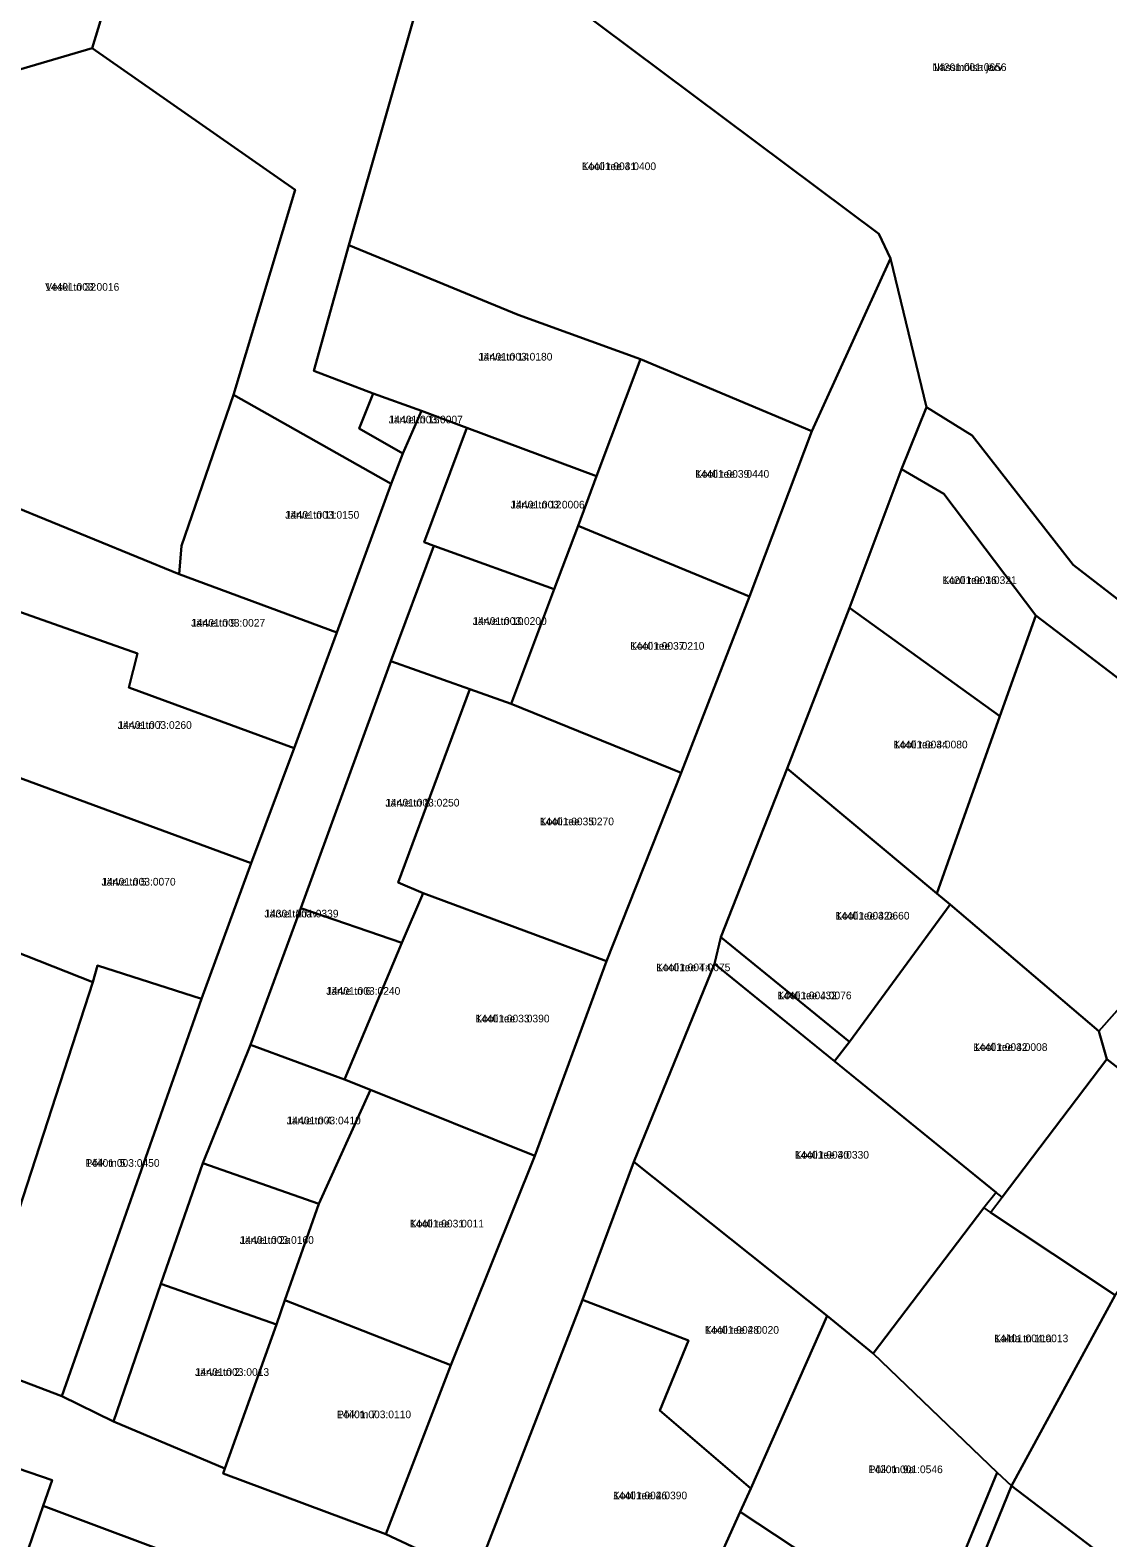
# Model space of a CAD drawing. Extents: x 640657 to 665127, y 6395726 to 6426831.
# Drawn here: x 650279.6 to 650490.5, y 6413110.9 to 6413405.9 of the extents above; entities that cross this region are included whole.
import ezdxf

# ---------------------------------------------------------------- set-up
doc = ezdxf.new("R2010")
doc.units = 0
for name, color, linetype in [('L_AADRESS', 7, 'Continuous'), ('PIIR', 7, 'Continuous'), ('TUNNUS', 7, 'Continuous')]:
    doc.layers.add(name, color=color, linetype=linetype)

msp = doc.modelspace()

# ---------------------------------------------------------------- linework, layer by layer
at = {"layer": 'PIIR'}
for points in [[(650239.68, 6413404.78), (650244.56, 6413436.52), (650296.67, 6413418.63), (650296.18, 6413417.03), (650291.72, 6413402.41), (650264, 6413394.25)], [(650296.18, 6413417.03), (650296.67, 6413418.63), (650313.26, 6413413.09), (650314.56, 6413413.9), (650316.99, 6413418.33), (650322.37, 6413433.84), (650323.18, 6413436.15), (650356.48, 6413416.32), (650356.93, 6413416.12), (650356.55, 6413414.99), (650341.99, 6413363.9), (650335.11, 6413339.3), (650346.72, 6413334.86), (650344.01, 6413327.96), (650352.56, 6413323.12), (650350.25, 6413317.19), (650319.38, 6413334.61), (650331.44, 6413374.73), (650291.72, 6413402.41)], [(650360.75, 6413429.64), (650445.67, 6413366.08), (650447.93, 6413361.29), (650432.57, 6413327.48), (650399.04, 6413341.57), (650375.12, 6413350.22), (650341.99, 6413363.9), (650356.55, 6413414.99), (650356.93, 6413416.12), (650357.5, 6413418.15)], [(650233.69, 6413371.67), (650239.68, 6413404.78), (650264, 6413394.25), (650291.72, 6413402.41), (650331.44, 6413374.73), (650319.38, 6413334.61), (650309.21, 6413305.01), (650308.77, 6413299.47), (650275.63, 6413313.03), (650260.72, 6413318.69), (650268.61, 6413358.41)], [(650390.43, 6413318.67), (650365.08, 6413328.14), (650356.21, 6413331.45), (650346.72, 6413334.86), (650335.11, 6413339.3), (650341.99, 6413363.9), (650375.12, 6413350.22), (650399.04, 6413341.57)], [(650447.93, 6413361.29), (650455.02, 6413332.18), (650450.1, 6413320), (650439.93, 6413292.9), (650427.74, 6413261.46), (650414.73, 6413228.41), (650413.5, 6413223.21), (650397.75, 6413184.5), (650387.68, 6413157.44), (650366.72, 6413103.36), (650349.21, 6413111.57), (650361.94, 6413144.67), (650378.35, 6413185.62), (650392.37, 6413223.71), (650406.97, 6413260.61), (650420.35, 6413295.13), (650432.57, 6413327.48)], [(650386.81, 6413308.95), (650390.43, 6413318.67), (650399.04, 6413341.57), (650432.57, 6413327.48), (650420.35, 6413295.13)], [(650319.38, 6413334.61), (650350.25, 6413317.19), (650339.6, 6413288.05), (650308.77, 6413299.47), (650309.21, 6413305.01)], [(650346.72, 6413334.86), (650356.21, 6413331.45), (650352.56, 6413323.12), (650344.01, 6413327.96)], [(650285.83, 6413138.63), (650313.15, 6413216.39), (650322.87, 6413242.9), (650331.25, 6413265.4), (650339.6, 6413288.05), (650350.25, 6413317.19), (650352.56, 6413323.12), (650356.21, 6413331.45), (650365.08, 6413328.14), (650356.68, 6413305.73), (650358.63, 6413305.03), (650350.16, 6413282.44), (650332.61, 6413234.09), (650322.72, 6413207.38), (650313.43, 6413184.18), (650305.16, 6413160.6), (650295.94, 6413133.65)], [(650450.1, 6413320), (650455.02, 6413332.18), (650463.94, 6413326.65), (650483.68, 6413301.28), (650535.03, 6413261.62), (650540.6, 6413257.3), (650543.8, 6413253.6), (650544.9, 6413251), (650553, 6413220.2), (650554.4, 6413215.1), (650558.34, 6413205.48), (650608.99, 6413156.91), (650603.97, 6413150.57), (650575.14, 6413177.06), (650575.61, 6413177.72), (650551.59, 6413195.75), (650543.11, 6413210.13), (650533.28, 6413247.75), (650511.53, 6413264.56), (650476.36, 6413291.39), (650458.4, 6413315.2)], [(650365.08, 6413328.14), (650390.43, 6413318.67), (650386.81, 6413308.95), (650382.17, 6413296.53), (650358.63, 6413305.03), (650356.68, 6413305.73)], [(650439.93, 6413292.9), (650450.1, 6413320), (650458.4, 6413315.2), (650476.36, 6413291.39), (650469.35, 6413271.66)], [(650339.6, 6413288.05), (650331.25, 6413265.4), (650298.94, 6413277.33), (650300.6, 6413283.97), (650267.91, 6413295.52), (650275.63, 6413313.03), (650308.77, 6413299.47)], [(650382.17, 6413296.53), (650386.81, 6413308.95), (650420.35, 6413295.13), (650406.97, 6413260.61), (650373.72, 6413274.09)], [(650350.16, 6413282.44), (650358.63, 6413305.03), (650382.17, 6413296.53), (650373.72, 6413274.09), (650365.62, 6413276.96)], [(650258.45, 6413274.81), (650267.91, 6413295.52), (650300.6, 6413283.97), (650298.94, 6413277.33), (650331.25, 6413265.4), (650322.87, 6413242.9), (650274.55, 6413260.7), (650277.16, 6413267.38)], [(650427.72, 6413261.48), (650439.93, 6413292.9), (650469.35, 6413271.66), (650463.49, 6413255.18), (650457.03, 6413237.01)], [(650511.53, 6413264.56), (650533.28, 6413247.75), (650522.77, 6413224.71), (650512.65, 6413202.51), (650494.29, 6413216.4), (650488.73, 6413210.04), (650459.61, 6413234.81), (650457.03, 6413237.01), (650463.49, 6413255.18), (650469.35, 6413271.66), (650476.36, 6413291.39)], [(650350.16, 6413282.44), (650365.62, 6413276.96), (650351.62, 6413239.13), (650356.48, 6413237.06), (650352.35, 6413227.35), (650332.61, 6413234.09)], [(650351.62, 6413239.13), (650365.62, 6413276.96), (650373.72, 6413274.09), (650406.97, 6413260.61), (650392.37, 6413223.71), (650356.48, 6413237.06)], [(650274.55, 6413260.7), (650322.87, 6413242.9), (650313.15, 6413216.39), (650292.79, 6413222.9), (650291.87, 6413219.64), (650262.95, 6413231.06)], [(650414.73, 6413228.41), (650427.74, 6413261.46), (650457.03, 6413237.01), (650459.61, 6413234.81), (650439.91, 6413207.97)], [(650246.99, 6413237.1), (650262.95, 6413231.06), (650291.87, 6413219.64), (650267.73, 6413145.46), (650223.38, 6413163.59)], [(650356.48, 6413237.06), (650392.37, 6413223.71), (650378.35, 6413185.62), (650346.19, 6413198.53), (650341.11, 6413200.59), (650352.35, 6413227.35)], [(650332.61, 6413234.09), (650352.35, 6413227.35), (650341.11, 6413200.59), (650322.72, 6413207.38)], [(650459.61, 6413234.81), (650488.73, 6413210.04), (650490.25, 6413204.53), (650469.82, 6413177.56), (650468.63, 6413178.49), (650436.96, 6413204.17), (650439.91, 6413207.97)], [(650414.73, 6413228.41), (650439.91, 6413207.97), (650436.96, 6413204.17), (650413.5, 6413223.21)], [(650291.87, 6413219.64), (650292.79, 6413222.9), (650313.15, 6413216.39), (650285.83, 6413138.63), (650267.73, 6413145.46)], [(650413.5, 6413223.21), (650468.63, 6413178.49), (650466.21, 6413175.44), (650444.55, 6413146.98), (650435.58, 6413154.3), (650397.75, 6413184.5)], [(650488.73, 6413210.04), (650494.29, 6413216.4), (650512.65, 6413202.51), (650530.63, 6413188.72), (650543.11, 6413210.13), (650551.59, 6413195.75), (650539.77, 6413179.73), (650533.54, 6413170.85), (650528.7, 6413174.65), (650513.56, 6413186.52), (650490.25, 6413204.53)], [(650322.72, 6413207.38), (650341.11, 6413200.59), (650346.19, 6413198.53), (650336.08, 6413176.24), (650313.43, 6413184.18)], [(650467.52, 6413174.58), (650469.82, 6413177.56), (650490.25, 6413204.53), (650513.56, 6413186.52), (650495.03, 6413162.84), (650491.92, 6413158.4)], [(650361.94, 6413144.67), (650329.47, 6413157.42), (650336.08, 6413176.24), (650346.19, 6413198.53), (650378.35, 6413185.62)], [(650313.43, 6413184.18), (650336.08, 6413176.24), (650329.47, 6413157.42), (650327.8, 6413152.65), (650305.16, 6413160.6)], [(650408.41, 6413149.51), (650387.68, 6413157.44), (650397.75, 6413184.5), (650435.58, 6413154.3), (650420.59, 6413120.53), (650402.81, 6413135.78)], [(650533.54, 6413170.85), (650539.77, 6413179.73), (650563.74, 6413161.57), (650555.61, 6413151.56), (650531.75, 6413126.74), (650536.61, 6413122.42), (650509.55, 6413091.33), (650495.52, 6413102.83), (650471.6, 6413121.03), (650491.92, 6413158.4), (650495.03, 6413162.84), (650510.82, 6413150.61), (650528.7, 6413174.65)], [(650466.21, 6413175.44), (650467.52, 6413174.58), (650491.92, 6413158.4), (650471.6, 6413121.03), (650468.8, 6413123.7), (650444.55, 6413146.98)], [(650317.71, 6413124.45), (650295.94, 6413133.65), (650305.16, 6413160.6), (650327.8, 6413152.65)], [(650327.8, 6413152.65), (650329.47, 6413157.42), (650361.94, 6413144.67), (650349.21, 6413111.57), (650317.37, 6413123.5), (650317.71, 6413124.45)], [(650387.68, 6413157.44), (650408.41, 6413149.51), (650402.81, 6413135.78), (650420.59, 6413120.53), (650418.55, 6413116), (650400.62, 6413076.11), (650366.72, 6413103.36)], [(650468.8, 6413123.7), (650455.57, 6413091.52), (650418.55, 6413116), (650420.59, 6413120.53), (650435.58, 6413154.3), (650444.55, 6413146.98)], [(650217.56, 6413097.01), (650231.92, 6413140.01), (650283.94, 6413122.19), (650282.18, 6413117.13), (650268.45, 6413077.48), (650237.31, 6413088.1)], [(650468.8, 6413123.7), (650471.6, 6413121.03), (650458.86, 6413089.63), (650456.25, 6413084.52), (650437.23, 6413047.33), (650434.02, 6413049.75), (650455.57, 6413091.52)], [(650471.6, 6413121.03), (650495.52, 6413102.83), (650484.02, 6413081.59), (650456.25, 6413084.52), (650458.86, 6413089.63)], [(650282.18, 6413117.13), (650312.64, 6413105.72), (650306.45, 6413086.49), (650335.26, 6413075.19), (650325.62, 6413049.27), (650271.11, 6413067.27), (650268.45, 6413077.48)], [(650418.55, 6413116), (650455.57, 6413091.52), (650434.02, 6413049.75), (650400.62, 6413076.11)]]:
    msp.add_lwpolyline(points, close=True, dxfattribs=at)
for points in [[(650535.03, 6413261.62), (650483.68, 6413301.28), (650463.94, 6413326.65), (650455.02, 6413332.18), (650447.93, 6413361.29), (650445.67, 6413366.08), (650360.75, 6413429.64)], [(650267.73, 6413145.46), (650285.83, 6413138.63), (650295.94, 6413133.65), (650317.71, 6413124.45), (650317.37, 6413123.5), (650349.21, 6413111.57), (650366.72, 6413103.36)], [(650312.64, 6413105.72), (650282.18, 6413117.13), (650283.94, 6413122.19), (650231.92, 6413140.01)]]:
    msp.add_lwpolyline(points, dxfattribs=at)

# ---------------------------------------------------------------- texts
at = {"layer": 'L_AADRESS'}
for s, p in [('Nässmõisa järv', (650456.15, 6413397.95)), ('Kooli tee 41', (650387.58, 6413378.56)), ('Veski tn 32', (650282.56, 6413354.95)), ('Järve tn 14', (650367.3, 6413341.29)), ('Järve tn 15', (650349.77, 6413328.99)), ('Kooli tee 39', (650409.72, 6413318.35)), ('Järve tn 11', (650329.51, 6413310.34)), ('Järve tn 12', (650373.61, 6413312.34)), ('Kooli tee 36', (650458.14, 6413297.55)), ('Järve tn 9', (650311.1, 6413289.21)), ('Järve tn 10', (650366.19, 6413289.56)), ('Kooli tee 37', (650397.04, 6413284.69)), ('Järve tn 7', (650296.74, 6413269.21)), ('Kooli tee 34', (650448.54, 6413265.39)), ('Järve tn 8', (650349.11, 6413254.01)), ('Kooli tee 35', (650379.34, 6413250.34)), ('Järve tn 5', (650293.58, 6413238.54)), ('Järve tänav', (650325.45, 6413232.3)), ('Kooli tee 32a', (650437.17, 6413231.89)), ('Kooli tee T4', (650402.12, 6413221.78)), ('Järve tn 6', (650337.54, 6413217.16)), ('Kooli tee J32', (650425.84, 6413216.29)), ('Kooli tee 33', (650366.74, 6413211.76)), ('Kooli tee 32', (650464.16, 6413206.18)), ('Järve tn 4', (650329.81, 6413191.81)), ('Põik tn 5', (650290.44, 6413183.5)), ('Kooli tee 30', (650429.24, 6413185.1)), ('Kooli tee 31', (650353.91, 6413171.63)), ('Järve tn 2a', (650320.62, 6413168.42)), ('Kooli tee 28', (650411.63, 6413150.82)), ('Kalda tn 11a', (650468.23, 6413149.17)), ('Järve tn 2', (650311.87, 6413142.58)), ('Põik tn 7', (650339.65, 6413134.29)), ('Põik tn 9a', (650443.67, 6413123.54)), ('Kooli tee 26', (650393.66, 6413118.43))]:
    msp.add_text(s, height=1.5, dxfattribs=at).set_placement(p)
at = {"layer": 'TUNNUS'}
for s, p in [('14201:001:0656', (650456.15, 6413397.95)), ('14401:003:0400', (650387.58, 6413378.56)), ('14401:003:0016', (650282.56, 6413354.95)), ('14401:003:0180', (650367.3, 6413341.29)), ('14401:003:0007', (650349.77, 6413328.99)), ('14401:003:0440', (650409.72, 6413318.35)), ('14401:003:0150', (650329.51, 6413310.34)), ('14401:003:0006', (650373.61, 6413312.34)), ('14201:001:0321', (650458.14, 6413297.55)), ('14401:003:0027', (650311.1, 6413289.21)), ('14401:003:0200', (650366.19, 6413289.56)), ('14401:003:0210', (650397.04, 6413284.69)), ('14401:003:0260', (650296.74, 6413269.21)), ('14401:004:0080', (650448.54, 6413265.39)), ('14401:003:0250', (650349.11, 6413254.01)), ('14401:003:0270', (650379.34, 6413250.34)), ('14401:003:0070', (650293.58, 6413238.54)), ('14301:001:0339', (650325.45, 6413232.3)), ('14401:004:0660', (650437.17, 6413231.89)), ('14401:004:0075', (650402.12, 6413221.78)), ('14401:003:0240', (650337.54, 6413217.16)), ('14401:004:0076', (650425.84, 6413216.29)), ('14401:003:0390', (650366.74, 6413211.76)), ('14401:004:0008', (650464.16, 6413206.18)), ('14401:003:0410', (650329.81, 6413191.81)), ('14401:003:0450', (650290.44, 6413183.5)), ('14401:004:0330', (650429.24, 6413185.1)), ('14401:003:0011', (650353.91, 6413171.63)), ('14401:003:0160', (650320.62, 6413168.42)), ('14401:004:0020', (650411.63, 6413150.82)), ('14401:004:0013', (650468.23, 6413149.17)), ('14401:003:0013', (650311.87, 6413142.58)), ('14401:003:0110', (650339.65, 6413134.29)), ('14201:001:0546', (650443.67, 6413123.54)), ('14401:004:0390', (650393.66, 6413118.43))]:
    msp.add_text(s, height=1.5, dxfattribs=at).set_placement(p)

doc.saveas('drawing.dxf')
